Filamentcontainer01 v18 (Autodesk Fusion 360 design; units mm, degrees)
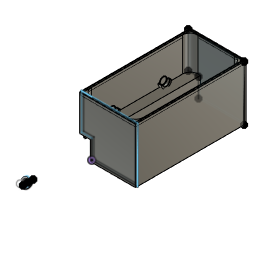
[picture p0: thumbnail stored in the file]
sketch "Skizze1" plane through (0, 0, 0) normal (0, 0, 1) x axis (1, 0, 0)
sketch "Skizze2" plane through (0, 0, 0) normal (0, 1, 0) x axis (1, 0, 0)
  line L1 (0, -37) -> (0, 0)
  line L2 (-20, -37) -> (0, -37)
  line L3 (-20, -107) -> (-20, -37)
  line L4 (-16, -107) -> (-20, -107)
  line L5 (-16, -41) -> (-16, -107)
  line L6 (4, -41) -> (-16, -41)
  line L7 (89, 0) -> (0, 0)
  line L8 (89, -107) -> (89, 0)
  line L9 (85, -107) -> (89, -107)
  line L10 (85, -4) -> (85, -107)
  line L11 (4, -4) -> (85, -4)
  line L12 (4, -4) -> (4, -41)
  point P1 (0, 0)
  point P2 (0, 0)
  point P9 (0, 0)
  point P3 (0, -37)
  point P4 (-20, -37)
  point P5 (-20, -107)
  point P6 (-16, -107)
  point P7 (-16, -41)
  point P8 (4, -41)
  point P10 (89, 0)
  point P11 (89, -107)
  point P12 (85, -107)
  point P13 (85, -4)
  point P14 (4, -4)
  coincident P1 P2
  vertical L1
  perpendicular L1 L2
  perpendicular L2 L3
  perpendicular L3 L4
  perpendicular L4 L5
  perpendicular L5 L6
  coincident P1 P9
  perpendicular L1 L7
  perpendicular L7 L8
  perpendicular L8 L9
  perpendicular L9 L10
  perpendicular L10 L11
  dimension "d1" distance P2 P3 = 37
  dimension "d2" distance P3 P4 = 20
  dimension "d3" distance P4 P5 = 70
  dimension "d4" distance P5 P6 = 4
  dimension "d5" distance P6 P7 = 66
  dimension "d6" distance P7 P8 = 20
  dimension "d7" distance P9 P10 = 89
  dimension "d8" distance P10 P11 = 107
  dimension "d9" distance P11 P12 = 4
  dimension "d10" distance P12 P13 = 103
  dimension "d11" distance P13 P14 = 81
extrude "Extrusion1" new body sketch "Skizze2" along normal blind 208
sketch "Skizze3" plane through (0, 0, 0) normal (0, 1, 0) x axis (1, 0, 0)
  line L1 (-20, -37) -> (-20, -107)
  line L2 (0, -37) -> (-20, -37)
  line L3 (0, 0) -> (0, -37)
  line L4 (89, 0) -> (0, 0)
  line L5 (89, -107) -> (89, 0)
  line L6 (-20, -107) -> (89, -107)
  point P1 (0, 0)
  point P5 (0, 0)
  vertical L1
  perpendicular L1 L2
  coincident P1 P5
  perpendicular L2 L3
  perpendicular L3 L4
  perpendicular L4 L5
extrude "Extrusion2" add sketch "Skizze3" against normal blind 4
sketch "Skizze4" plane through (0, 208, 0) normal (0, 1, 0) x axis (-1, 0, 0)
  line L1 (0, 37) -> (0, 0)
  line L2 (20, 37) -> (0, 37)
  line L3 (20, 107) -> (20, 37)
  line L4 (16, 107) -> (20, 107)
  line L5 (16, 41) -> (16, 107)
  line L6 (-4, 41) -> (16, 41)
  line L7 (-4, 4) -> (-4, 41)
  line L8 (-85, 4) -> (-4, 4)
  line L9 (-85, 107) -> (-85, 4)
  line L10 (-89, 107) -> (-85, 107)
  line L11 (-89, 0) -> (-89, 107)
  line L12 (0, 0) -> (-89, 0)
  line L13 (-89, 0) -> (-89, 107)
  line L14 (0, 37) -> (0, 0)
  line L15 (20, 37) -> (0, 37)
  line L16 (20, 107) -> (20, 37)
  line L17 (20, 107) -> (-89, 107)
  point P12 (-89, 107)
  point P14 (-89, 107)
  point P13 (-89, 0)
  point P15 (-89, 0)
  point P2 (0, 0)
  point P16 (0, 0)
  point P3 (0, 37)
  point P17 (0, 37)
  point P18 (0, 37)
  point P4 (20, 37)
  point P19 (20, 37)
  point P20 (20, 37)
  point P5 (20, 107)
  point P21 (20, 107)
  point P22 (-89, 107)
  point P23 (20, 107)
  coincident P12 P14
  coincident P13 P15
  coincident P2 P16
  coincident P3 P17
  coincident P3 P18
  coincident P4 P19
  coincident P4 P20
  coincident P5 P21
  coincident P12 P22
  coincident P5 P23
extrude "Extrusion3" add sketch "Skizze4" along normal blind 4
sketch "Skizze5" plane through (0, 0, 0) normal (0, 1, 0) x axis (-1, 0, 0)
sketch "Skizze6" plane through (0, 0, 0) normal (1, 0, 0) x axis (0, 1, 0)
  line L1 (-140, 29.9701) -> (-137.9999, 29.9701)
  line L2 (-120, 30) -> (-122, 30)
  line L3 (-120, 30) -> (-122.5, 30)
  line L4 (-140, 29.9701) -> (-137.5, 29.9944)
  circle C1 centre (-130, 30) radius 6
  circle C2 centre (-130, 30) radius 7
  arc A1 centre (-130, 30) radius 8 clockwise from (-122, 30) to (-137.9999, 29.9701)
  arc A2 centre (-130, 30) radius 10 clockwise from (-120, 30) to (-140, 29.9701)
  circle C3 centre (-130, 30) radius 1
  arc A3 centre (-130, 30) radius 7.5 clockwise from (-122.5, 30) to (-137.5, 29.9944)
  point P2 (-130, 30)
  point P4 (-130, 30)
  point P10 (-140, 29.9701)
  point P3 (-130, 30)
  point P9 (-130, 30)
  point P12 (-130, 30)
  concentric C1 C2
  coincident P2 P4
  horizontal L1
  horizontal L2
  coincident L1 P10
  coincident P3 P9
  concentric A1 C3
  coincident P9 P12
  parallel L2 L3
  dimension "d18" diameter C1 = 12
  dimension "d19" diameter C2 = 14
  dimension "d21" diameter C3 = 2
  dimension "d29" radius A3 = 7.5
extrude "Extrusion4" new body sketch "Skizze6" profile of A1 L1 L2 A2 along normal blind 5.5 bodies "Kl1a"
extrude "Extrusion5" new body sketch "Skizze6" profile of C1 C2 along normal blind 0.5 bodies "Kl1b"
extrude "Extrusion6" new body sketch "Skizze6" profile of C3 along normal blind 0.3 bodies "Kl1c"
fillet "Abrundung1" radius 1
sketch "Skizze7" plane through (5.5, 0, 0) normal (1, 0, 0) x axis (0, 1, 0)
  line L1 (-140, 29.9701) -> (-137.9999, 29.9701)
  line L2 (-122, 30) -> (-120, 30)
  line L3 (-137, 30) -> (-130, 30)
  line L4 (-123, 30) -> (-130, 30)
  line L5 (-137, 30) -> (-140, 29.9701)
  line L6 (-120, 30) -> (-123, 30)
  arc A1 centre (-130, 30) radius 10 clockwise from (-120, 30) to (-140, 29.9701)
  arc A2 centre (-130, 30) radius 8 clockwise from (-122, 30) to (-137.9999, 29.9701)
  arc A3 centre (-130, 30) radius 7 clockwise from (-123, 30) to (-137, 30)
  arc A4 centre (-130, 30) radius 10 clockwise from (-120, 30) to (-140, 29.9701)
  point P5 (-130, 30)
  point P7 (-130, 30)
  point P3 (-140, 29.9701)
  point P11 (-140, 29.9701)
  point P4 (-120, 30)
  point P12 (-120, 30)
  point P10 (-130, 30)
  point P13 (-140, 29.9701)
  point P14 (-120, 30)
  coincident P5 P7
  coincident P3 P11
  coincident P4 P12
  coincident P5 P10
  coincident P3 P13
  coincident P4 P14
  dimension "d30" angle L3 L4 = 180
extrude "Extrusion7" add sketch "Skizze7" profile of L1 A1 L2 A2 A3 A4 L5 L6 along normal blind 1
copy_paste_bodies "Körper kopieren/einfügen1"
move "Verschieben1"
copy_paste_bodies "Körper kopieren/einfügen2"
move "Verschieben2"
copy_paste_bodies "Körper kopieren/einfügen3"
move "Verschieben3"
move "Verschieben4"
move "Verschieben5"
move "Verschieben6"
move "Verschieben7"
move "Verschieben8"
move "Verschieben10"
move "Verschieben9"
move "Verschieben11"
fillet "Abrundung2" radius 15
fillet "Abrundung3" radius 15
fillet "Abrundung4" radius 15
sketch "Skizze11" plane through (0, 0, 107) normal (0, 0, 1) x axis (-1, 0, 0)
  line L1 (-89, 0) -> (-85, 0)
  line L2 (-89, -212) -> (-89, 0)
  line L3 (20, -212) -> (-89, -212)
  line L4 (20, 0) -> (20, -212)
  line L5 (16, 0) -> (20, 0)
  line L6 (16, -193) -> (16, 0)
  line L7 (-70, -208) -> (1, -208)
  line L8 (-85, -15) -> (-85, -193)
  line L9 (-85, 0) -> (-70, 0)
  line L10 (141.4744, -242.6152) -> (248.6744, -242.6152)
  line L11 (141.4744, -28.4152) -> (141.4744, -242.6152)
  line L12 (248.6744, -28.4152) -> (141.4744, -28.4152)
  line L13 (248.6744, -242.6152) -> (248.6744, -28.4152)
  arc A1 centre (1, -193) radius 15 clockwise from (16, -193) to (1, -208)
  arc A2 centre (-70, -193) radius 15 clockwise from (-70, -208) to (-85, -193)
  arc A3 centre (-70, -15) radius 15 clockwise from (-85, -15) to (-70, 0)
  point P18 (248.6744, -242.6152)
  point P19 (141.4744, -242.6152)
  point P21 (248.6744, -28.4152)
  horizontal L10
  vertical L11
  horizontal L12
  vertical L13
  dimension "d45" distance P18 P19 = 107.2
  dimension "d46" distance P18 P21 = 214.2
extrude "Extrusion10" new body sketch "Skizze11" profile of L10 L11 L12 L13 along normal blind 1
sketch "Skizze12" plane through (0, 0, 108) normal (0, 0, 1) x axis (-1, 0, 0)
  line L1 (141.4744, -28.4152) -> (248.6744, -28.4152)
  line L2 (141.4744, -242.6152) -> (141.4744, -28.4152)
  line L3 (248.6744, -242.6152) -> (141.4744, -242.6152)
  line L4 (248.6744, -28.4152) -> (248.6744, -242.6152)
  line L5 (143.6648, -240.4028) -> (246.4648, -240.4028)
  line L6 (143.6648, -30.6028) -> (143.6648, -240.4028)
  line L7 (246.4648, -30.6028) -> (143.6648, -30.6028)
  line L8 (246.4648, -240.4028) -> (246.4648, -30.6028)
  line L9 (248.6663, -28.399) -> (246.4663, -28.399)
  line L10 (248.6663, -30.599) -> (248.6663, -28.399)
  line L11 (246.4663, -30.599) -> (248.6663, -30.599)
  line L12 (246.4663, -28.399) -> (246.4663, -30.599)
  point P6 (246.4648, -240.4028)
  point P7 (143.6648, -240.4028)
  point P9 (246.4648, -30.6028)
  point P10 (246.4663, -28.399)
  point P13 (246.4663, -30.599)
  point P11 (248.6663, -28.399)
  horizontal L5
  vertical L6
  horizontal L7
  vertical L8
  horizontal L9
  vertical L10
  horizontal L11
  vertical L12
  dimension "d49" distance P6 P7 = 102.8
  dimension "d50" distance P6 P9 = 209.8
  dimension "d74" distance P10 P13 = 2.2
  dimension "d75" distance P10 P11 = 2.2
extrude "Extrusion11" cut sketch "Skizze12" profile of L5 L6 L7 L8 against normal blind 1
extrude "Extrusion12" add of existing geometry blind 4
move "Verschieben14"
fillet "Abrundung5" radius 15
move_face "Fläche verschieben1"
move_face "Fläche verschieben2"
move_face "Fläche verschieben3"
move "Verschieben15"
move_face "Fläche verschieben4"
move_face "Fläche verschieben5"
move_face "Fläche verschieben6"
move "Verschieben16"
combine "Kombinieren"
fillet "Abrundung6" radius 1
fillet "Abrundung7" radius 1
fillet "Abrundung8" radius 1
move "Verschieben17"
move "Verschieben18"
move "Verschieben19"
move "Verschieben20"
move "Verschieben21"
move "Verschieben22"
sketch "Skizze15" plane through (0, 0, 37) normal (0, 0, -1) x axis (1, 0, 0)
  line L1 (-20, -212) -> (-20, 4)
  line L2 (0, -212) -> (-20, -212)
  line L3 (0, 4) -> (0, -212)
  line L4 (-20, 4) -> (0, 4)
  line L5 (-13.5, -212) -> (-20, -212)
  line L6 (-13.5, 4) -> (-13.5, -212)
  line L7 (-20, 4) -> (-13.5, 4)
  line L8 (-20, -212) -> (-20, 4)
  line L9 (-8.7, -212) -> (-13.5, -212)
  line L10 (-8.7, 4) -> (-8.7, -212)
  line L11 (-13.5, 4) -> (-8.7, 4)
  line L12 (-13.5, -212) -> (-13.5, 4)
  point P8 (-13.5, 4)
  point P3 (-20, -212)
  point P6 (-20, -212)
  point P7 (-13.5, -212)
  point P10 (-8.7, -212)
  horizontal L5
  vertical L6
  horizontal L7
  vertical L8
  coincident L4 P8
  coincident P3 P6
  horizontal L9
  vertical L10
  horizontal L11
  vertical L12
  dimension "d76" distance P6 P7 = 6.5
  dimension "d77" distance P7 P10 = 4.8
extrude "Extrusion15" add sketch "Skizze15" profile of L2 L4 L6 L9 L10 L11 L12 along normal blind 5
fillet "Abrundung17" radius 2
fillet "Abrundung18" radius 2
fillet "Abrundung19" radius 2
fillet "Abrundung20" radius 2
fillet "Abrundung21" radius 0.5
fillet "Abrundung22" radius 0.5
fillet "Abrundung23" radius 0.5
fillet "Abrundung24" radius 0.5
fillet "Abrundung25" radius 0.5
fillet "Abrundung26" radius 1
fillet "Abrundung27" radius 1
extrude "Extrusion14" add blind 11
fillet "Abrundung11" radius 1.5
fillet "Abrundung12" radius 1.5
fillet "Abrundung13" radius 1.5
fillet "Abrundung15" radius 1.5
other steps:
base_feature "Basiselement1" bodies "Kl2a", "Kl2b", "Kl2c"
base_feature "Basiselement2" bodies "Kl1a", "Kl1b", "Kl1c", "Kl3a", "Kl3b", "Kl3c"
base_feature "Basiselement3" bodies "Kl3a", "Kl3b", "Kl3c", "Kl4a", "Kl4b", "Kl4c"
named bodies: "Kl1a", "Kl1b", "Kl1c", "Kl2a", "Kl2b", "Kl2c", "Kl3a", "Kl3b", "Kl3c", "Kl4a", "Kl4b", "Kl4c"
